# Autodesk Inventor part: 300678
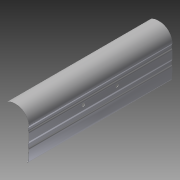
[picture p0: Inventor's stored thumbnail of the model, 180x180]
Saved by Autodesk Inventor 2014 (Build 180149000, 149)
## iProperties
Created: 2007-11
Part Number: 300678
Document SubType Name: Modeling
Designer: TH
Density: 7.85 g/cm^3
Mass: 505.093 g
Surface Area: 1294.91 cm^2
Volume: 64.343 cm^3
Material: Steel
Description: LOWER PAN
Appearance: Steel
Component Category: Back Component
Author: TH
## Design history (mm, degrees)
sketch "Sketch2" dims "d29" = 1
  geometry: L1 (-34, 0)-(-34, -31.438); L2 (0, 34)-(5.035, 34); L3 (-32.206, -86.75)-(-28.206, -86.75); L4 (-36.751, -26.12)-(-27.66, -147.38); L5 (0, -189.321)-(0, 104.266) reference; L6 (22.947, 27.676)-(23.492, 28.515); L7 (0, 0)-(4.974, 0); L8 (-31.278, -85.75)-(-28.206, -85.75); L9 (0, 33)-(4.974, 33); L10 (22.947, 27.676)-(23.492, 28.515); L11 (-28.206, -85.75)-(-28.206, -86.75); L12 (-31, -3)-(-31, -13); L13 (-31, -40)-(-31, -51); L14 (-33, -0.616)-(-31, -3); L15 (-31, -13)-(-33, -14.678); L16 (-34, -14.212)-(-32, -12.534); L17 (-32, -12.534)-(-32, -3.364); L18 (-32, -3.364)-(-34, -0.98); L19 (-31, -40)-(-32.986, -37.633); L20 (-31, -51)-(-32.831, -52.536); L21 (-33.839, -52.077)-(-32, -50.534); L22 (-32, -50.534)-(-32, -40.364); L23 (-32, -40.364)-(-33.985, -37.999); L24 (-33, 0)-(-33, -0.616); L25 (-33, -2.172)-(-33, -13.373); L26 (-33, -14.678)-(-33, -31.438); A1 r 34 centre (0, 0) between (0, 34) and (-34, 0); A2 r 1993.935 centre (1956.148, 62.325) between (-35.25, -38.216) and (-27.979, -135.196); A3 r 34 centre (4.974, 0) between (23.492, 28.515) and (5.035, 34); A4 r 33 centre (0, 0) between (0, 33) and (-33, 0); A5 r 33 centre (4.974, 0) between (22.947, 27.676) and (4.974, 33); 4 further points
  constraints: 50 end point, 9 point on circle, 7 perpendicular, 5 centre point, 5 parallel, 5 point on line, 4 midpoint, 2 collinear, 2 tangent, 1 vertical, 17 other
  dimensions: "d0" = 86.75 distance from line of L3 L7.start; "d1" = 11.61188 dimension on L4.start L4.end; "d2" = 4.28767 deg angle of L4 L5; "d3" = 31.4384 vertical distance of point (0, 0) L1.end; "d4" = 32.20571 distance from line of L3.start L5; "d5" = 61.94974 vertical distance of point (0, 0) point (-33.604, -61.95); "d6" = 33.60445 distance from line of L5 point (-33.604, -61.95); "d7" = 4 distance of L3.start L3.end; "d8" = 33 deg angle of L6 L5; "d9" = 4.97386 distance of L7.start L7.end; "d10" = 18.51776 horizontal distance of L7.end L6.end; "d11" = 1 radial gap between concentric circles of A1 A4; "d13" = 31 distance between parallel lines of L5 L12; "d14" = 31 distance between parallel lines of L5 L13; "d15" = 40 deg angle of L14 L5; "d16" = 10 distance of L12.end L12.start; "d17" = 3 vertical distance of point (0, 0) L12.start; "d18" = 1 distance between parallel lines of L12 L17; "d19" = 1 distance between parallel lines of L14 L18; "d20" = 1 distance between parallel lines of L15 L16; "d21" = 40 distance from line of L7 L13.start; "d22" = 11 distance of L13.start L13.end; "d23" = 1 distance between parallel lines of L22 L13; "d24" = 1 distance between parallel lines of L20 L21; "d25" = 1 distance between parallel lines of L19 L23; "d26" = 28.51479 vertical distance of L6.end point (0, 0); "d27" = 1 distance between parallel lines of L1 L24; "d28" = 1 distance between parallel lines of L1 L26
extrude "Extrusion1" new body sketch "Sketch2" stored distance "d30" = 385; taper "d31" = 0 deg
fillet "Fillet1" dims "d32" = 6
fillet "Fillet2" dims "d33" = 5, "d34" = 7
fillet "Fillet3" dims "d35" = 3
fillet "Fillet4" dims "d36" = 4
sketch "Sketch3"
  geometry: L1 (0, -192.5)-(14.599, -192.5) reference; L2 (8.301, -46.451)-(8.301, 43.549); L3 (-79.462, 0)-(89.588, 0) reference; L4 (31.438, 269.516)-(31.438, -269.516) reference; 1 further point
  constraints: 2 end point, 1 perpendicular
  dimensions: "d37" = 90.00002 distance of L2.start L2.end; "d38" = 23.13709 distance between parallel lines of L2 L4; "d39" = 46.4513 distance from line of L3 L2.start
hole "Hole1" sketch "Sketch3" at (8.301, -46.451), (8.301, 43.549) diameter "d40" = 9; stored, may be unused: countersink angle "d44" = 90 deg, drill point angle "d46" = 118 deg; dims "d41" = 6, "d42" = 4, "d43" = 2, "d45" = 8
workaxis "Work Axis1"
workaxis "Work Axis2"
body "Solid1"
other parameters: "d12" = 1
